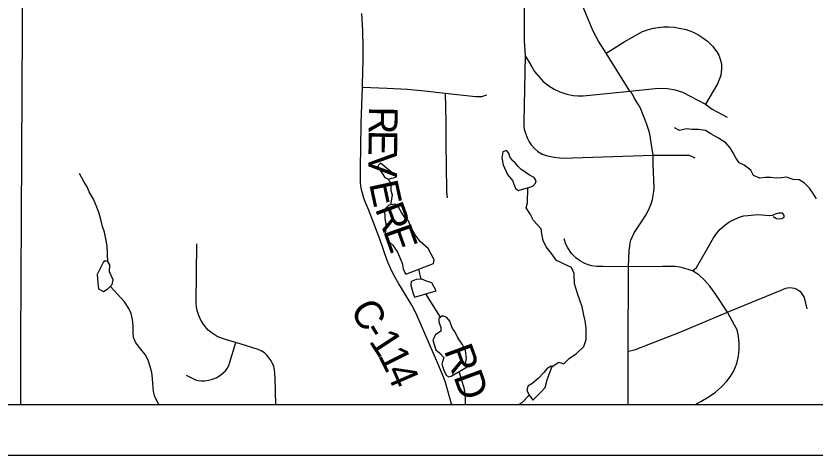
# Model space of a CAD drawing. Extents: x 0 to 34, y 0 to 22.
# Drawn here: x 6.431 to 8.013, y 14 to 14.868 of the extents above; entities that cross this region are included whole.
import ezdxf

# ---------------------------------------------------------------- set-up
doc = ezdxf.new("R2010")
doc.units = 0
for name, color, linetype in [('Default', 7, 'Continuous'), ('GM_X_County_Road', 7, 'Continuous'), ('GM_X_County_Road_Text', 7, 'Continuous'), ('GM_X_Interstate_Route', 7, 'Continuous'), ('GM_X_Minor_Lake', 7, 'Continuous'), ('GM_X_Minor_River', 7, 'Continuous'), ('GM_X_State_Route', 7, 'Continuous'), ('GM_X_Township_Road', 7, 'Continuous'), ('SH_Cut_Line', 7, 'Continuous'), ('SH_Data', 7, 'Continuous')]:
    doc.layers.add(name, color=color, linetype=linetype)

msp = doc.modelspace()

# ---------------------------------------------------------------- linework, layer by layer
at = {"layer": 'Default'}
msp.add_lwpolyline([(3.2815, 15.7537), (3.2811, 15.7294), (3.2832, 14.8896), (3.2841, 14.501), (3.2822, 14.2781), (3.2808, 14.1155), (3.2807, 14.1), (8.4439, 14.1), (8.4391, 14.4529), (8.4328, 14.555), (8.4328, 14.5554), (8.4608, 15.4787), (8.4608, 15.9241)], dxfattribs=at)
at = {"layer": 'GM_X_County_Road'}
msp.add_lwpolyline([(7.2933, 14.1), (7.2924, 14.103), (7.2857, 14.1266), (7.2809, 14.1431), (7.2774, 14.1529), (7.2659, 14.1808), (7.2315, 14.2604), (7.2241, 14.2769), (7.2192, 14.2876), (7.2145, 14.2962), (7.2074, 14.3085), (7.2013, 14.3183), (7.1883, 14.3389), (7.1789, 14.3556), (7.1721, 14.3694), (7.1657, 14.3846), (7.1576, 14.408), (7.1509, 14.4266), (7.1384, 14.4602), (7.1286, 14.4856), (7.1228, 14.4993), (7.1195, 14.5083), (7.1166, 14.5179), (7.1144, 14.5243), (7.1134, 14.5321), (7.1127, 14.539), (7.1125, 14.5459), (7.1124, 14.5562), (7.1125, 14.5702), (7.1132, 14.6075), (7.1143, 14.6564), (7.1164, 14.7273), (7.1173, 14.7622), (7.1183, 14.7765), (7.1183, 14.7894), (7.1183, 14.8062), (7.1171, 14.8398), (7.1154, 14.8732)], dxfattribs=at)
at = {"layer": 'GM_X_Interstate_Route'}
msp.add_lwpolyline([(6.44, 14.1), (6.4402, 14.223), (6.4444, 14.9673), (6.444, 15.0095)], dxfattribs=at)
at = {"layer": 'GM_X_Minor_Lake'}
for points in [[(7.43, 14.5653), (7.4246, 14.5709), (7.4189, 14.5777), (7.4143, 14.5818), (7.4085, 14.5901), (7.4062, 14.5973), (7.402, 14.6022), (7.3948, 14.5995), (7.3923, 14.5881), (7.3954, 14.5741), (7.4039, 14.5548), (7.4135, 14.5427), (7.4193, 14.5272), (7.4254, 14.5231), (7.436, 14.5262), (7.4462, 14.529), (7.4542, 14.5317), (7.459, 14.5378), (7.4605, 14.5424), (7.4563, 14.5492), (7.4471, 14.5533)], [(7.152, 14.5771), (7.1475, 14.5729), (7.1476, 14.5672), (7.1526, 14.5623), (7.1564, 14.5562), (7.161, 14.5487), (7.1675, 14.5453), (7.1739, 14.5473), (7.1788, 14.5485), (7.1845, 14.5512)], [(7.1845, 14.5512), (7.152, 14.5771)], [(7.4471, 14.5533), (7.43, 14.5653)], [(7.2572, 14.3791), (7.2583, 14.3863), (7.2464, 14.4086), (7.2311, 14.4222), (7.2207, 14.4357), (7.213, 14.4493), (7.2076, 14.4633), (7.2007, 14.4697), (7.1938, 14.4795), (7.188, 14.4901), (7.1808, 14.4961), (7.1687, 14.4941), (7.1604, 14.4857), (7.161, 14.4678), (7.1634, 14.453), (7.1616, 14.439), (7.1643, 14.4265), (7.1766, 14.4148), (7.1858, 14.4012), (7.192, 14.3872), (7.1951, 14.3793), (7.1974, 14.3679), (7.2025, 14.3577)], [(6.616, 14.362), (6.6163, 14.3761), (6.6121, 14.3825), (6.6071, 14.384), (6.603, 14.3809), (6.5974, 14.3687), (6.5915, 14.3572), (6.5924, 14.3405), (6.5936, 14.3284), (6.6035, 14.3232), (6.6125, 14.3286), (6.6212, 14.3374), (6.623, 14.3462)], [(7.2025, 14.3577), (7.2572, 14.3791)], [(6.623, 14.3462), (6.616, 14.362)], [(7.2626, 14.3249), (7.2542, 14.3407), (7.2431, 14.3441), (7.2344, 14.3481), (7.223, 14.3473), (7.2128, 14.343), (7.2125, 14.3362), (7.2164, 14.3214), (7.2199, 14.3119)], [(7.2199, 14.3119), (7.2626, 14.3249)], [(7.3242, 14.1747), (7.3207, 14.1808), (7.3225, 14.191), (7.3205, 14.2066), (7.3143, 14.219), (7.3055, 14.2315), (7.2993, 14.2443), (7.2947, 14.25), (7.2913, 14.2587), (7.2897, 14.2644), (7.2839, 14.2723), (7.2752, 14.2756), (7.2677, 14.2702), (7.2677, 14.2634), (7.272, 14.2524), (7.272, 14.2448), (7.2615, 14.2375), (7.2559, 14.228), (7.2586, 14.2189), (7.2621, 14.2079), (7.2694, 14.2023), (7.2774, 14.1929), (7.2737, 14.1803), (7.2776, 14.1674), (7.2827, 14.1572), (7.2876, 14.1546), (7.2925, 14.1562)], [(7.2925, 14.1562), (7.3242, 14.1747)], [(7.4724, 14.1271), (7.4784, 14.1336), (7.4825, 14.1489), (7.4884, 14.1653), (7.4925, 14.1752), (7.4902, 14.1755), (7.4823, 14.1713), (7.4748, 14.1625), (7.4646, 14.151), (7.4518, 14.141), (7.4439, 14.1364), (7.4421, 14.1276), (7.4471, 14.1174), (7.454, 14.1084)], [(7.454, 14.1084), (7.4724, 14.1271)]]:
    msp.add_lwpolyline(points, dxfattribs=at)
at = {"layer": 'GM_X_Minor_River'}
for points in [[(8.0158, 14.5068), (8.0093, 14.5174), (8.0015, 14.5275), (7.9919, 14.5376), (7.9816, 14.544), (7.9695, 14.5449), (7.9565, 14.5493), (7.9463, 14.548), (7.9357, 14.5475), (7.9247, 14.5489), (7.9145, 14.5491), (7.9035, 14.5478), (7.8909, 14.553), (7.8859, 14.5636), (7.8725, 14.5732), (7.8626, 14.5777), (7.856, 14.5878), (7.8505, 14.5976), (7.8444, 14.6074), (7.8359, 14.6176), (7.8214, 14.6265), (7.8065, 14.6354), (7.7961, 14.6417), (7.7821, 14.6438), (7.7685, 14.6436), (7.7582, 14.6454), (7.7442, 14.6421), (7.7347, 14.6469)], [(6.6126, 14.3817), (6.611, 14.414), (6.6087, 14.4273), (6.6055, 14.4405), (6.602, 14.4523), (6.5985, 14.4659), (6.5946, 14.4799), (6.5907, 14.4901), (6.5837, 14.506), (6.5756, 14.5207), (6.5714, 14.5306), (6.5652, 14.5408), (6.5564, 14.5566)], [(7.1729, 14.4948), (7.176, 14.5139), (7.1735, 14.5222), (7.1735, 14.5363), (7.168, 14.5455)], [(7.4925, 14.1752), (7.5057, 14.1836), (7.5156, 14.1803), (7.5268, 14.1914), (7.54, 14.2003), (7.5547, 14.2145), (7.5595, 14.2282), (7.5598, 14.2407), (7.5597, 14.251), (7.5573, 14.2654), (7.5549, 14.2768), (7.5514, 14.2934), (7.5471, 14.3063), (7.5432, 14.3173), (7.5397, 14.3279), (7.5362, 14.3389), (7.536, 14.359), (7.5306, 14.3707), (7.5123, 14.3796), (7.5009, 14.3848), (7.4906, 14.3988), (7.4802, 14.412), (7.4744, 14.4245), (7.4716, 14.4377), (7.4704, 14.4472), (7.4555, 14.4638), (7.449, 14.4759), (7.4405, 14.4891), (7.4431, 14.4986), (7.444, 14.5284)], [(7.2328, 14.348), (7.2281, 14.3677)], [(6.7139, 14.1), (6.7119, 14.1028), (6.7054, 14.1153), (6.7026, 14.1255), (6.7017, 14.1415), (6.7009, 14.1513), (6.6993, 14.1631), (6.6961, 14.1752), (6.6922, 14.1873), (6.6861, 14.199), (6.678, 14.2096), (6.6681, 14.222), (6.663, 14.2322), (6.6626, 14.2425), (6.6625, 14.2554), (6.6612, 14.2683), (6.6585, 14.28), (6.6542, 14.2899), (6.6457, 14.3027), (6.6174, 14.3336)], [(7.271, 14.2727), (7.2422, 14.3187)], [(7.3207, 14.1), (7.3206, 14.1094), (7.3197, 14.1208), (7.3185, 14.1302), (7.315, 14.1435), (7.3081, 14.1653)], [(7.4257, 14.1), (7.4325, 14.104), (7.4468, 14.1181)]]:
    msp.add_lwpolyline(points, dxfattribs=at)
at = {"layer": 'GM_X_State_Route'}
msp.add_lwpolyline([(6.44, 14.1), (6.4402, 14.223), (6.4444, 14.9673), (6.444, 15.0095)], dxfattribs=at)
at = {"layer": 'GM_X_Township_Road'}
for points in [[(7.4367, 14.9206), (7.4371, 14.8191), (7.4386, 14.7893), (7.4361, 14.6584), (7.4364, 14.6509), (7.4369, 14.6448), (7.4393, 14.6363), (7.4427, 14.6276), (7.447, 14.6196), (7.4507, 14.6133), (7.457, 14.6065), (7.464, 14.6005), (7.4723, 14.5949), (7.4827, 14.5915), (7.496, 14.5888), (7.5127, 14.5874), (7.6921, 14.593), (7.7638, 14.5934), (7.775, 14.5875)], [(7.6428, 14.1), (7.6428, 14.2053), (7.6434, 14.372), (7.6446, 14.4044), (7.6458, 14.4134), (7.6465, 14.4194), (7.6482, 14.4252), (7.6547, 14.4393), (7.6703, 14.4633), (7.6775, 14.4744), (7.6836, 14.4854), (7.688, 14.4965), (7.6906, 14.5057), (7.6921, 14.5133), (7.6933, 14.5212), (7.6945, 14.5292), (7.6925, 14.574), (7.6923, 14.5835), (7.6921, 14.593), (7.6879, 14.622), (7.686, 14.6322), (7.6836, 14.6419), (7.6797, 14.6536), (7.6756, 14.664), (7.6711, 14.6755), (7.6676, 14.6846), (7.6625, 14.694), (7.6555, 14.7054), (7.6514, 14.7139), (7.646, 14.7197), (7.5989, 14.7948), (7.5838, 14.8184), (7.5735, 14.8384), (7.5504, 14.8939)], [(7.5989, 14.7948), (7.6201, 14.8079), (7.6349, 14.8174), (7.6511, 14.8266), (7.6709, 14.8375), (7.6831, 14.8419), (7.6926, 14.8445), (7.702, 14.8455), (7.7129, 14.847), (7.7229, 14.8468), (7.734, 14.8462), (7.7438, 14.8441), (7.7575, 14.8414), (7.7699, 14.8373), (7.7808, 14.8319), (7.7907, 14.8254), (7.7995, 14.8186), (7.8095, 14.8089), (7.8183, 14.7973), (7.822, 14.7907), (7.8251, 14.7828), (7.8273, 14.7738), (7.8275, 14.7648), (7.8259, 14.7508), (7.8196, 14.7344), (7.7958, 14.6939)], [(7.4386, 14.7893), (7.442, 14.7842), (7.4456, 14.7793), (7.4517, 14.768), (7.4572, 14.7585), (7.465, 14.7493), (7.4747, 14.7386), (7.4853, 14.7304), (7.4965, 14.7236), (7.5074, 14.7185), (7.5212, 14.7139), (7.5336, 14.7112), (7.543, 14.7103), (7.5539, 14.7103), (7.5934, 14.7141), (7.646, 14.7197), (7.7024, 14.7255), (7.7207, 14.725), (7.7358, 14.7224), (7.7506, 14.7175), (7.7958, 14.6939)], [(7.1164, 14.7273), (7.1657, 14.7253), (7.2059, 14.7236), (7.2393, 14.7205), (7.2805, 14.7156), (7.3406, 14.709), (7.3532, 14.7091), (7.3628, 14.7121)], [(7.2805, 14.7156), (7.282, 14.6584), (7.2817, 14.6133), (7.2825, 14.5733), (7.2832, 14.5212), (7.2843, 14.509)], [(7.7958, 14.6939), (7.809, 14.6842), (7.8389, 14.6683)], [(7.7704, 14.3641), (7.7781, 14.371), (7.798, 14.4049), (7.8118, 14.4294), (7.8186, 14.4388), (7.8251, 14.4465), (7.8339, 14.4546), (7.8422, 14.4606), (7.854, 14.4667), (7.8642, 14.4711), (7.8717, 14.473), (7.8797, 14.474), (7.8998, 14.4755), (7.9216, 14.474), (7.9291, 14.4742), (7.9347, 14.4771), (7.9412, 14.4793), (7.9475, 14.4788), (7.9507, 14.474), (7.9507, 14.4701), (7.9471, 14.4672), (7.9422, 14.4664), (7.9362, 14.4674), (7.9301, 14.4711)], [(6.9449, 14.1), (6.9439, 14.1519), (6.9433, 14.1613), (6.9425, 14.1687), (6.941, 14.1751), (6.9385, 14.1811), (6.9356, 14.1862), (6.9318, 14.1918), (6.9272, 14.1975), (6.9229, 14.2018), (6.9161, 14.2063), (6.91, 14.209), (6.8661, 14.2225), (6.8494, 14.2273), (6.8392, 14.2305), (6.8287, 14.2346), (6.8192, 14.2408), (6.8109, 14.247), (6.8025, 14.2573), (6.7963, 14.2667), (6.7928, 14.2758), (6.7893, 14.2855), (6.7882, 14.2928), (6.7874, 14.3011), (6.7883, 14.4174)], [(7.7757, 14.1), (7.7864, 14.1056), (7.8011, 14.1143), (7.8157, 14.124), (7.8278, 14.1346), (7.8381, 14.1462), (7.845, 14.1545), (7.8513, 14.165), (7.8581, 14.1812), (7.8614, 14.1953), (7.8627, 14.2086), (7.8625, 14.2209), (7.8614, 14.2353), (7.8586, 14.2473), (7.8533, 14.2571), (7.8397, 14.2825), (7.815, 14.3196), (7.8043, 14.3339), (7.7941, 14.3455), (7.7825, 14.3564), (7.7704, 14.3641), (7.7482, 14.3707), (7.7364, 14.3726), (7.727, 14.3731), (7.711, 14.3731), (7.6434, 14.372), (7.5923, 14.373), (7.5809, 14.3729), (7.571, 14.3743), (7.5636, 14.3763), (7.5555, 14.3794), (7.5465, 14.3845), (7.5388, 14.3903), (7.5308, 14.3985), (7.523, 14.4098), (7.5196, 14.4169), (7.516, 14.4278)], [(7.8397, 14.2825), (7.844, 14.2844), (7.9456, 14.326), (7.9546, 14.3302), (7.9614, 14.331), (7.9677, 14.3307), (7.9715, 14.3297), (7.9766, 14.3283), (7.9824, 14.3242), (7.9861, 14.3198), (7.9913, 14.3115), (7.9964, 14.2889)], [(7.6428, 14.2053), (7.6494, 14.2064), (7.6574, 14.2086), (7.7473, 14.2437), (7.8397, 14.2825)], [(6.7675, 14.1582), (6.7858, 14.149), (6.7914, 14.1474), (6.7976, 14.1466), (6.8047, 14.1466), (6.8117, 14.1477), (6.8195, 14.1501), (6.827, 14.1528), (6.8332, 14.1565), (6.8408, 14.1625), (6.8451, 14.1668), (6.8487, 14.1713), (6.8518, 14.177), (6.8542, 14.1835), (6.8661, 14.2225)]]:
    msp.add_lwpolyline(points, dxfattribs=at)
at = {"layer": 'SH_Cut_Line'}
msp.add_lwpolyline([(3.2807, 14.1), (8.9, 14.1), (8.9, 20.9), (3.2826, 20.9), (3.2843, 20.6124), (3.2845, 20.5998), (3.2888, 19.8918), (3.2901, 19.68), (3.2904, 19.1173), (3.2907, 18.4315), (3.2837, 17.3796), (3.2835, 17.0107), (3.2832, 16.3898), (3.2829, 15.8433), (3.2815, 15.7537), (3.2811, 15.7294), (3.2832, 14.8896), (3.2841, 14.501), (3.2822, 14.2781), (3.2808, 14.1155)], close=True, dxfattribs=at)
at = {"layer": 'SH_Data'}
for p, q in [((2.1, 14.1), (8.9, 14.1)), ((2, 14), (9, 14))]:
    msp.add_line(p, q, dxfattribs=at)

# ---------------------------------------------------------------- texts
at = {"layer": 'GM_X_County_Road_Text'}
for s, height, rotation, p in [('R', 0.0568, 269.1648, (7.1298, 14.6897)), ('E', 0.0568, 269.1643, (7.1291, 14.643)), ('V', 0.0568, 269.5927, (7.1285, 14.6)), ('E', 0.0568, 282.2, (7.1295, 14.5367)), ('R', 0.0568, 290.2437, (7.1409, 14.487)), ('E', 0.0568, 289.5518, (7.157, 14.4434)), ('C', 0.0568, 300.6913, (7.0908, 14.2873)), ('-', 0.0568, 301.7867, (7.1152, 14.2461)), ('1', 0.0568, 303.1076, (7.1283, 14.2251)), ('1', 0.0568, 296.728, (7.1466, 14.1972)), ('RD', 0.05682, 290.1584, (7.2773, 14.2068)), ('4', 0.0568, 293.3913, (7.1619, 14.1668))]:
    msp.add_text(s, height=height, rotation=rotation, dxfattribs=at).set_placement(p)

doc.saveas('drawing.dxf')
